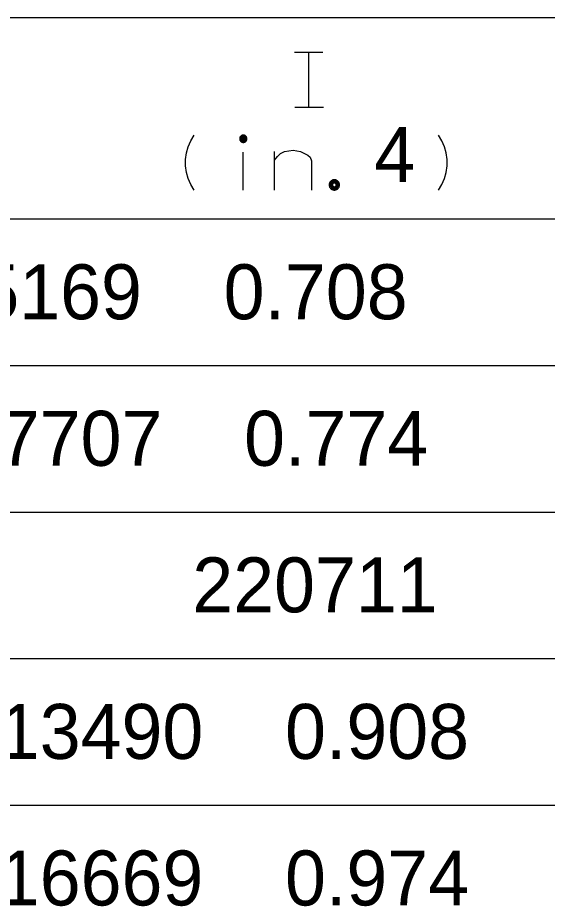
# Model space of a CAD drawing. Extents: x 635698 to 639877, y 296617 to 300175.
# Drawn here: x 639284.27 to 639313.16, y 298759.79 to 298808.29 of the extents above; entities that cross this region are included whole.
import ezdxf

# ---------------------------------------------------------------- set-up
doc = ezdxf.new("R2010")
doc.units = 0
for name, color, linetype in [('1', 7, 'Continuous'), ('2', 7, 'Continuous'), ('3', 7, 'Continuous')]:
    doc.layers.add(name, color=color, linetype=linetype)

msp = doc.modelspace()

# ---------------------------------------------------------------- linework, layer by layer
at = {"layer": '2'}
for p, q in [((639405.108, 298808.295), (639199.161, 298808.295)), ((639405.108, 298797.295), (638853.272, 298797.295)), ((639405.108, 298789.295), (638853.272, 298789.295)), ((639405.108, 298781.295), (638853.272, 298781.295)), ((639405.108, 298773.295), (638853.272, 298773.295)), ((639405.108, 298765.295), (638853.272, 298765.295))]:
    msp.add_line(p, q, dxfattribs=at)
at = {"layer": '3'}
for p, q in [((639299.364, 298806.415), (639300.919, 298806.415)), ((639299.394, 298803.41), (639300.948, 298803.41))]:
    msp.add_line(p, q, dxfattribs=at)
for points in [[(639299.793, 298806.413), (639300.502, 298806.413)], [(639300.148, 298803.413), (639300.148, 298806.413)], [(639299.793, 298803.413), (639300.502, 298803.413)], [(639293.897, 298798.886), (639293.708, 298799.194), (639293.566, 298799.524), (639293.471, 298799.855), (639293.424, 298800.209), (639293.424, 298800.564), (639293.471, 298800.918), (639293.566, 298801.248), (639293.708, 298801.579), (639293.897, 298801.886)], [(639296.776, 298801.688), (639296.774, 298801.709), (639296.772, 298801.729), (639296.766, 298801.749), (639296.759, 298801.769), (639296.749, 298801.787), (639296.738, 298801.805), (639296.725, 298801.821), (639296.71, 298801.836), (639296.694, 298801.848), (639296.677, 298801.86), (639296.658, 298801.869), (639296.639, 298801.877), (639296.619, 298801.882), (639296.598, 298801.885), (639296.578, 298801.886), (639296.557, 298801.885), (639296.536, 298801.882), (639296.516, 298801.877), (639296.497, 298801.869), (639296.478, 298801.86), (639296.461, 298801.848), (639296.445, 298801.836), (639296.43, 298801.821), (639296.417, 298801.805), (639296.406, 298801.787), (639296.397, 298801.769), (639296.389, 298801.749), (639296.384, 298801.729), (639296.38, 298801.709), (639296.379, 298801.688), (639296.38, 298801.667), (639296.384, 298801.647), (639296.389, 298801.627), (639296.397, 298801.608), (639296.406, 298801.589), (639296.417, 298801.572), (639296.43, 298801.556), (639296.445, 298801.541), (639296.461, 298801.528), (639296.478, 298801.517), (639296.497, 298801.507), (639296.516, 298801.5), (639296.536, 298801.495), (639296.557, 298801.491), (639296.578, 298801.49), (639296.598, 298801.491), (639296.619, 298801.495), (639296.639, 298801.5), (639296.658, 298801.507), (639296.677, 298801.517), (639296.694, 298801.528), (639296.71, 298801.541), (639296.725, 298801.556), (639296.738, 298801.572), (639296.749, 298801.589), (639296.759, 298801.608), (639296.766, 298801.627), (639296.772, 298801.647), (639296.774, 298801.667), (639296.776, 298801.688)], [(639296.716, 298801.688), (639296.715, 298801.703), (639296.713, 298801.717), (639296.709, 298801.731), (639296.704, 298801.744), (639296.697, 298801.757), (639296.689, 298801.769), (639296.68, 298801.781), (639296.67, 298801.791), (639296.659, 298801.8), (639296.647, 298801.808), (639296.634, 298801.814), (639296.62, 298801.819), (639296.606, 298801.823), (639296.592, 298801.826), (639296.578, 298801.826), (639296.563, 298801.826), (639296.549, 298801.823), (639296.535, 298801.819), (639296.521, 298801.814), (639296.508, 298801.808), (639296.496, 298801.8), (639296.485, 298801.791), (639296.475, 298801.781), (639296.466, 298801.769), (639296.458, 298801.757), (639296.452, 298801.744), (639296.446, 298801.731), (639296.442, 298801.717), (639296.44, 298801.703), (639296.439, 298801.688), (639296.44, 298801.674), (639296.442, 298801.66), (639296.446, 298801.645), (639296.452, 298801.632), (639296.458, 298801.619), (639296.466, 298801.607), (639296.475, 298801.596), (639296.485, 298801.586), (639296.496, 298801.577), (639296.508, 298801.569), (639296.521, 298801.562), (639296.535, 298801.557), (639296.549, 298801.553), (639296.563, 298801.551), (639296.578, 298801.55), (639296.592, 298801.551), (639296.606, 298801.553), (639296.62, 298801.557), (639296.634, 298801.562), (639296.647, 298801.569), (639296.659, 298801.577), (639296.67, 298801.586), (639296.68, 298801.596), (639296.689, 298801.607), (639296.697, 298801.619), (639296.704, 298801.632), (639296.709, 298801.645), (639296.713, 298801.66), (639296.715, 298801.674), (639296.716, 298801.688)], [(639296.656, 298801.688), (639296.655, 298801.696), (639296.654, 298801.704), (639296.652, 298801.712), (639296.649, 298801.72), (639296.645, 298801.727), (639296.641, 298801.734), (639296.636, 298801.74), (639296.63, 298801.746), (639296.623, 298801.751), (639296.616, 298801.756), (639296.609, 298801.759), (639296.602, 298801.762), (639296.594, 298801.764), (639296.586, 298801.766), (639296.578, 298801.766), (639296.569, 298801.766), (639296.561, 298801.764), (639296.553, 298801.762), (639296.546, 298801.759), (639296.538, 298801.756), (639296.532, 298801.751), (639296.525, 298801.746), (639296.519, 298801.74), (639296.514, 298801.734), (639296.51, 298801.727), (639296.506, 298801.72), (639296.503, 298801.712), (639296.501, 298801.704), (639296.5, 298801.696), (639296.5, 298801.688), (639296.5, 298801.68), (639296.501, 298801.672), (639296.503, 298801.664), (639296.506, 298801.656), (639296.51, 298801.649), (639296.514, 298801.643), (639296.519, 298801.636), (639296.525, 298801.63), (639296.532, 298801.625), (639296.538, 298801.621), (639296.546, 298801.617), (639296.553, 298801.614), (639296.561, 298801.612), (639296.569, 298801.611), (639296.578, 298801.61), (639296.586, 298801.611), (639296.594, 298801.612), (639296.602, 298801.614), (639296.609, 298801.617), (639296.616, 298801.621), (639296.623, 298801.625), (639296.63, 298801.63), (639296.636, 298801.636), (639296.641, 298801.643), (639296.645, 298801.649), (639296.649, 298801.656), (639296.652, 298801.664), (639296.654, 298801.672), (639296.655, 298801.68), (639296.656, 298801.688)], [(639296.596, 298801.688), (639296.596, 298801.69), (639296.595, 298801.692), (639296.594, 298801.694), (639296.594, 298801.696), (639296.593, 298801.697), (639296.592, 298801.699), (639296.591, 298801.7), (639296.59, 298801.701), (639296.588, 298801.703), (639296.586, 298801.704), (639296.585, 298801.705), (639296.583, 298801.706), (639296.581, 298801.706), (639296.579, 298801.706), (639296.578, 298801.706), (639296.576, 298801.706), (639296.574, 298801.706), (639296.572, 298801.706), (639296.57, 298801.705), (639296.568, 298801.704), (639296.567, 298801.703), (639296.566, 298801.701), (639296.564, 298801.7), (639296.563, 298801.699), (639296.562, 298801.697), (639296.561, 298801.696), (639296.56, 298801.694), (639296.56, 298801.692), (639296.56, 298801.69), (639296.56, 298801.688), (639296.56, 298801.686), (639296.56, 298801.685), (639296.56, 298801.683), (639296.561, 298801.681), (639296.562, 298801.679), (639296.563, 298801.678), (639296.564, 298801.676), (639296.566, 298801.675), (639296.567, 298801.674), (639296.568, 298801.673), (639296.57, 298801.672), (639296.572, 298801.671), (639296.574, 298801.671), (639296.576, 298801.67), (639296.578, 298801.67), (639296.579, 298801.67), (639296.581, 298801.671), (639296.583, 298801.671), (639296.585, 298801.672), (639296.586, 298801.673), (639296.588, 298801.674), (639296.59, 298801.675), (639296.591, 298801.676), (639296.592, 298801.678), (639296.593, 298801.679), (639296.594, 298801.681), (639296.594, 298801.683), (639296.595, 298801.685), (639296.596, 298801.686), (639296.596, 298801.688)], [(639307.219, 298798.886), (639307.408, 298799.194), (639307.55, 298799.524), (639307.645, 298799.855), (639307.692, 298800.209), (639307.692, 298800.564), (639307.645, 298800.918), (639307.55, 298801.248), (639307.408, 298801.579), (639307.219, 298801.886)], [(639296.578, 298798.886), (639296.578, 298800.965)], [(639298.28, 298800.516), (639298.446, 298800.729), (639298.611, 298800.894), (639298.824, 298800.989), (639299.297, 298801.06), (639299.699, 298800.989), (639300.101, 298800.8), (639300.22, 298800.682), (639300.29, 298800.493), (639300.29, 298798.886)], [(639298.28, 298798.886), (639298.28, 298800.989)], [(639301.83, 298799.171), (639301.829, 298799.201), (639301.824, 298799.231), (639301.816, 298799.259), (639301.806, 298799.287), (639301.792, 298799.314), (639301.776, 298799.339), (639301.757, 298799.362), (639301.736, 298799.383), (639301.713, 298799.402), (639301.688, 298799.418), (639301.661, 298799.432), (639301.633, 298799.442), (639301.605, 298799.45), (639301.575, 298799.455), (639301.545, 298799.456), (639301.515, 298799.455), (639301.486, 298799.45), (639301.457, 298799.442), (639301.429, 298799.432), (639301.403, 298799.418), (639301.377, 298799.402), (639301.354, 298799.383), (639301.333, 298799.362), (639301.314, 298799.339), (639301.298, 298799.314), (639301.284, 298799.287), (639301.274, 298799.259), (639301.266, 298799.231), (639301.261, 298799.201), (639301.26, 298799.171), (639301.261, 298799.141), (639301.266, 298799.112), (639301.274, 298799.083), (639301.284, 298799.055), (639301.298, 298799.029), (639301.314, 298799.004), (639301.333, 298798.981), (639301.354, 298798.959), (639301.377, 298798.941), (639301.403, 298798.925), (639301.429, 298798.911), (639301.457, 298798.9), (639301.486, 298798.893), (639301.515, 298798.888), (639301.545, 298798.886), (639301.575, 298798.888), (639301.605, 298798.893), (639301.633, 298798.9), (639301.661, 298798.911), (639301.688, 298798.925), (639301.713, 298798.941), (639301.736, 298798.959), (639301.757, 298798.981), (639301.776, 298799.004), (639301.792, 298799.029), (639301.806, 298799.055), (639301.816, 298799.083), (639301.824, 298799.112), (639301.829, 298799.141), (639301.83, 298799.171)], [(639301.77, 298799.171), (639301.769, 298799.195), (639301.765, 298799.218), (639301.759, 298799.241), (639301.751, 298799.263), (639301.74, 298799.284), (639301.727, 298799.304), (639301.712, 298799.322), (639301.696, 298799.338), (639301.677, 298799.353), (639301.658, 298799.366), (639301.637, 298799.377), (639301.615, 298799.385), (639301.592, 298799.391), (639301.569, 298799.395), (639301.545, 298799.396), (639301.522, 298799.395), (639301.498, 298799.391), (639301.475, 298799.385), (639301.453, 298799.377), (639301.433, 298799.366), (639301.413, 298799.353), (639301.394, 298799.338), (639301.378, 298799.322), (639301.363, 298799.304), (639301.35, 298799.284), (639301.339, 298799.263), (639301.331, 298799.241), (639301.325, 298799.218), (639301.321, 298799.195), (639301.32, 298799.171), (639301.321, 298799.148), (639301.325, 298799.124), (639301.331, 298799.102), (639301.339, 298799.08), (639301.35, 298799.059), (639301.363, 298799.039), (639301.378, 298799.021), (639301.394, 298799.004), (639301.413, 298798.989), (639301.433, 298798.977), (639301.453, 298798.966), (639301.475, 298798.957), (639301.498, 298798.951), (639301.522, 298798.948), (639301.545, 298798.946), (639301.569, 298798.948), (639301.592, 298798.951), (639301.615, 298798.957), (639301.637, 298798.966), (639301.658, 298798.977), (639301.677, 298798.989), (639301.696, 298799.004), (639301.712, 298799.021), (639301.727, 298799.039), (639301.74, 298799.059), (639301.751, 298799.08), (639301.759, 298799.102), (639301.765, 298799.124), (639301.769, 298799.148), (639301.77, 298799.171)], [(639301.71, 298799.171), (639301.709, 298799.189), (639301.706, 298799.205), (639301.702, 298799.222), (639301.696, 298799.238), (639301.688, 298799.254), (639301.679, 298799.268), (639301.668, 298799.282), (639301.655, 298799.294), (639301.642, 298799.305), (639301.628, 298799.314), (639301.612, 298799.322), (639301.596, 298799.328), (639301.579, 298799.332), (639301.562, 298799.335), (639301.545, 298799.336), (639301.528, 298799.335), (639301.511, 298799.332), (639301.494, 298799.328), (639301.478, 298799.322), (639301.462, 298799.314), (639301.448, 298799.305), (639301.434, 298799.294), (639301.422, 298799.282), (639301.411, 298799.268), (639301.402, 298799.254), (639301.394, 298799.238), (639301.388, 298799.222), (639301.383, 298799.205), (639301.381, 298799.189), (639301.38, 298799.171), (639301.381, 298799.154), (639301.383, 298799.137), (639301.388, 298799.12), (639301.394, 298799.104), (639301.402, 298799.089), (639301.411, 298799.074), (639301.422, 298799.061), (639301.434, 298799.049), (639301.448, 298799.038), (639301.462, 298799.029), (639301.478, 298799.02), (639301.494, 298799.014), (639301.511, 298799.01), (639301.528, 298799.007), (639301.545, 298799.006), (639301.562, 298799.007), (639301.579, 298799.01), (639301.596, 298799.014), (639301.612, 298799.02), (639301.628, 298799.029), (639301.642, 298799.038), (639301.655, 298799.049), (639301.668, 298799.061), (639301.679, 298799.074), (639301.688, 298799.089), (639301.696, 298799.104), (639301.702, 298799.12), (639301.706, 298799.137), (639301.709, 298799.154), (639301.71, 298799.171)], [(639301.65, 298799.171), (639301.65, 298799.182), (639301.648, 298799.193), (639301.645, 298799.204), (639301.641, 298799.214), (639301.636, 298799.224), (639301.63, 298799.233), (639301.623, 298799.242), (639301.616, 298799.249), (639301.607, 298799.256), (639301.598, 298799.262), (639301.588, 298799.267), (639301.577, 298799.271), (639301.567, 298799.274), (639301.556, 298799.276), (639301.545, 298799.276), (639301.534, 298799.276), (639301.523, 298799.274), (639301.512, 298799.271), (639301.502, 298799.267), (639301.492, 298799.262), (639301.483, 298799.256), (639301.475, 298799.249), (639301.467, 298799.242), (639301.46, 298799.233), (639301.454, 298799.224), (639301.449, 298799.214), (639301.445, 298799.204), (639301.442, 298799.193), (639301.441, 298799.182), (639301.44, 298799.171), (639301.441, 298799.16), (639301.442, 298799.149), (639301.445, 298799.139), (639301.449, 298799.128), (639301.454, 298799.119), (639301.46, 298799.109), (639301.467, 298799.101), (639301.475, 298799.093), (639301.483, 298799.086), (639301.492, 298799.08), (639301.502, 298799.075), (639301.512, 298799.071), (639301.523, 298799.068), (639301.534, 298799.067), (639301.545, 298799.066), (639301.556, 298799.067), (639301.567, 298799.068), (639301.577, 298799.071), (639301.588, 298799.075), (639301.598, 298799.08), (639301.607, 298799.086), (639301.616, 298799.093), (639301.623, 298799.101), (639301.63, 298799.109), (639301.636, 298799.119), (639301.641, 298799.128), (639301.645, 298799.139), (639301.648, 298799.149), (639301.65, 298799.16), (639301.65, 298799.171)]]:
    msp.add_lwpolyline(points, dxfattribs=at)

# ---------------------------------------------------------------- texts
at = {"layer": '1'}
for s, p in [('  0.175     679     14.20      73400      4369      5169    0.708', (639201.833, 298791.837)), ('  0.191     743     17.57     135418      6319      7707    0.774', (639201.833, 298783.837)), ('220711      8499     10495    0.841', (639293.794, 298775.837)), ('  0.224     871     24.57     331440     10892     13490    0.908', (639201.833, 298767.837)), ('  0.241     935     28.18     469733     13490     16669    0.974', (639201.833, 298759.837))]:
    msp.add_text(s, height=3, dxfattribs=at).set_placement(p)
at = {"layer": '3'}
msp.add_text('4', height=3, dxfattribs=at).set_placement((639303.722, 298799.327))

doc.saveas('drawing.dxf')
